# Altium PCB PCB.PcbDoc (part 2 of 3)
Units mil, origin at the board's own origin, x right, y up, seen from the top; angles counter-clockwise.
Board outline 5900 x 2310 mil, 2 copper layers (Top Layer, Bottom Layer), stack 62 mil thick; 158 components, 83 nets, 407 pads, 547 vias.
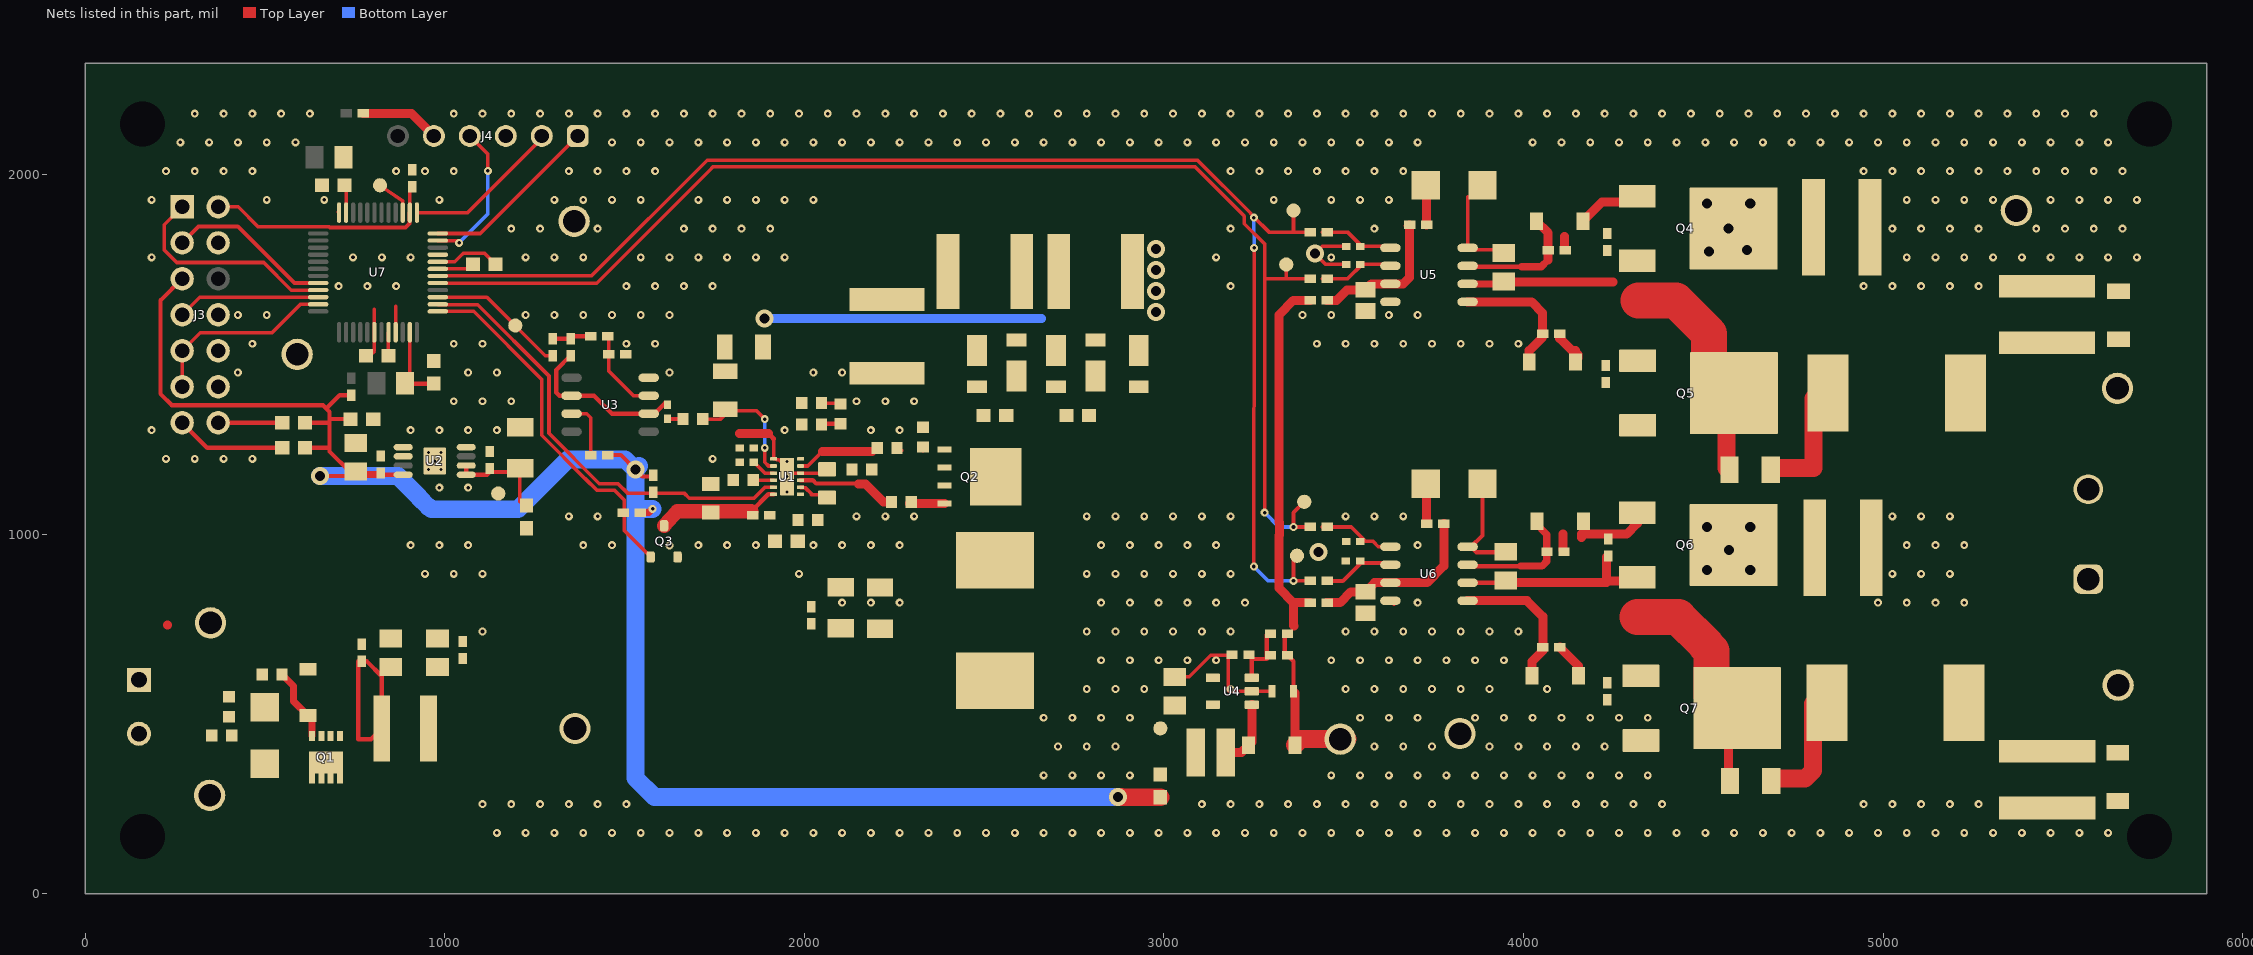
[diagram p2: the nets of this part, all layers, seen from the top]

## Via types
v1: diameter 22, hole 10, Top Layer to Bottom Layer, 506 vias
v2: diameter 50, hole 28, Top Layer to Bottom Layer, tented both sides, 22 vias
v3: diameter 22, hole 10, Top Layer to Bottom Layer, tented both sides, 11 vias
v4: diameter 19.68, hole 7.87, Top Layer to Bottom Layer, tented both sides, 8 vias

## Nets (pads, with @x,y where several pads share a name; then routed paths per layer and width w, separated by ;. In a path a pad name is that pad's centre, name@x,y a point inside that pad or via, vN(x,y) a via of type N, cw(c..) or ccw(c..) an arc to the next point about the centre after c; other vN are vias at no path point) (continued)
GND: C2.2 C3.2 C4.2 C5.2 C9.1 C10.2 C11.2 C12.2 C14.1 C15.2 C16.2 C17.2 C18.2 C19.2 C20.2 C21.2 C22.2 C23.2 C24.2 C25.2 C26.2 C28.2 C31.2 C32.2 C33.2 C34.2 C35.2 C36.2 C38.2 C39.2 C40.2 C41.2 C42.2 C43.2 C44.2 C45.2 C46.2 C47.2 C48.2 D3.2 J1.1 J3.4 J3.8 J3.10 J3.12 J4.3 Q3.2 Q5.3 Q7.3 R1.1 R9.1 R10.1 R11.1 R15.1 R23.1 R31.1 R39.1 R43.1 TP5.1 TP6.1 TP7.1 TP8.1 U1.4 U1.7 U1.13@1952.05,1160 U2.4 U2.5 U2.6 U2.9 U3.4 U4.2 U5.4 U6.4 U7.12 U7.30 U7.33 U7.44 U7.45 | length 1319.8
  Top Layer w10: U7.12@704.64,1895.75 U7.12@706.25,1894.14 ; C47.2@780.97,1495.75 790.97,1495.75 804.68,1509.45 U7.30@804.68,1561.46 804.68,1624.68 ; U7.33@863.73,1561.46 863.73,1633.73 ; U7.44@980.86,1757.32 1027.76,1757.32 1050.43,1780 1051.91,1780 1053.49,1781.57 1109.92,1781.57 C48.2@1141.5,1750 ; 1914.65,1265.35 U1.7@1914.65,1209.21 1920.24,1209.21 1921.05,1208.4 1922.46,1208.4 1923.54,1207.32 1928.67,1207.32 1937.36,1198.63 1937.36,1186.5 U1.13@1952.05,1171.81 ; v4(1952.05,1202.32) U1.13@1952.44,1202.72 ; U1.13@1961.89,1169.84 U1.4@1989.45,1169.84 C14.1@2057.4,1169.84 ; C14.1@2063.3,1180.5 C14.1@2063.3,1193.3 ; C26.2@3030,603.29 3070,603.29 3130,663.29 R23.1@3186.38,663.29 ; R23.1@3178.66,655.57 3178.66,564.78 3180.16,563.29 U4.2@3244.13,563.29 C28.2@3300,563.29 ; C36.2@3503.15,1750 3450,1750 v2(3420,1780) 3440,1800 C33.2@3503.15,1800 ; U6.4@3639.48,805 U6.4@3639.48,815
  Top Layer w14: 1900,1280 1914.65,1265.35
  Top Layer w25: 229.87,747 230,747.13 ; 1820,1280 1900,1280
  other v1: 1145.19,169.5 1225.19,169.5 1305.19,169.5 1385.19,169.5 1465.19,169.5 1545.19,169.5 1625.19,169.5 1705.19,169.5 1785.19,169.5 1865.19,169.5 1945.19,169.5 2025.19,169.5 2105.19,169.5 2185.19,169.5 2265.19,169.5 2345.19,169.5 2425.19,169.5 2505.19,169.5 2585.19,169.5 2665.19,169.5 2745.19,169.5 2825.19,169.5 2905.19,169.5 2985.19,169.5 3065.19,169.5 3145.19,169.5 3225.19,169.5 3305.19,169.5 3385.19,169.5 3465.19,169.5 3545.19,169.5 3625.19,169.5 3705.19,169.5 3785.19,169.5 3865.19,169.5 3945.19,169.5 4025.19,169.5 4105.19,169.5 4185.19,169.5 4265.19,169.5 4345.19,169.5 4425.19,169.5 4505.19,169.5 4585.19,169.5 4665.19,169.5 4745.19,169.5 4825.19,169.5 4905.19,169.5 4985.19,169.5 5065.19,169.5 5145.19,169.5 5225.19,169.5 5305.19,169.5 5385.19,169.5 5465.19,169.5 5545.19,169.5 5625.19,169.5 1105.19,249.5 1185.19,249.5 1265.19,249.5 1345.19,249.5 1425.19,249.5 1505.19,249.5 3105.19,249.5 3185.19,249.5 3265.19,249.5 3345.19,249.5 3425.19,249.5 3505.19,249.5 3585.19,249.5 3665.19,249.5 3745.19,249.5 3825.19,249.5 3905.19,249.5 3985.19,249.5 4065.19,249.5 4145.19,249.5 4225.19,249.5 4305.19,249.5 4385.19,249.5 4945.19,249.5 5025.19,249.5 5105.19,249.5 5185.19,249.5 5265.19,249.5 2665.19,329.5 2745.19,329.5 2825.19,329.5 2905.19,329.5 3465.19,329.5 3545.19,329.5 3625.19,329.5 3705.19,329.5 3785.19,329.5 3865.19,329.5 3945.19,329.5 4025.19,329.5 4105.19,329.5 4185.19,329.5 4265.19,329.5 4345.19,329.5 2705.19,409.5 2785.19,409.5 2865.19,409.5 3585.19,409.5 3665.19,409.5 3745.19,409.5 3905.19,409.5 3985.19,409.5 4065.19,409.5 4145.19,409.5 4225.19,409.5 2665.19,489.5 2745.19,489.5 2825.19,489.5 2905.19,489.5 3545.19,489.5 3625.19,489.5 3705.19,489.5 3865.19,489.5 3945.19,489.5 4025.19,489.5 4105.19,489.5 4185.19,489.5 4265.19,489.5 4345.19,489.5 2785.19,569.5 2865.19,569.5 2945.19,569.5 3185.19,569.5 3505.19,569.5 3585.19,569.5 3665.19,569.5 3745.19,569.5 3825.19,569.5 3905.19,569.5 4065.19,569.5 2825.19,649.5 2905.19,649.5 2985.19,649.5 3065.19,649.5 3145.19,649.5 3465.19,649.5 3545.19,649.5 3625.19,649.5 3705.19,649.5 3785.19,649.5 3865.19,649.5 3945.19,649.5 1105.19,729.5 2785.19,729.5 2865.19,729.5 2945.19,729.5 3025.19,729.5 3105.19,729.5 3185.19,729.5 3505.19,729.5 3585.19,729.5 3665.19,729.5 3745.19,729.5 3825.19,729.5 3905.19,729.5 3985.19,729.5 2105.19,809.5 2185.19,809.5 2265.19,809.5 2825.19,809.5 2905.19,809.5 2985.19,809.5 3065.19,809.5 3145.19,809.5 3225.19,809.5 3705.19,809.5 4985.19,809.5 5065.19,809.5 5145.19,809.5 5225.19,809.5 945.19,889.5 1025.19,889.5 1105.19,889.5 1985.19,889.5 2785.19,889.5 2865.19,889.5 2945.19,889.5 3025.19,889.5 3105.19,889.5 3185.19,889.5 5025.19,889.5 5105.19,889.5 5185.19,889.5 1625,968.5 905.19,969.5 985.19,969.5 1065.19,969.5 1385.19,969.5 1465.19,969.5 1705.19,969.5 1785.19,969.5 1865.19,969.5 2025.19,969.5 2105.19,969.5 2185.19,969.5 2265.19,969.5 2825.19,969.5 2905.19,969.5 2985.19,969.5 3065.19,969.5 3145.19,969.5 3705.19,969.5 5065.19,969.5 5145.19,969.5 5225.19,969.5 1345.19,1049.5 1425.19,1049.5 2145.19,1049.5 2225.19,1049.5 2305.19,1049.5 2785.19,1049.5 2865.19,1049.5 2945.19,1049.5 3025.19,1049.5 3105.19,1049.5 3185.19,1049.5 3505.19,1049.5 3585.19,1049.5 3665.19,1049.5 5025.19,1049.5 5105.19,1049.5 5185.19,1049.5 985.19,1129.5 1065.19,1129.5 225.19,1209.5 305.19,1209.5 385.19,1209.5 465.19,1209.5 1745.19,1209.5 185.19,1289.5 905.19,1289.5 985.19,1289.5 1065.19,1289.5 1145.19,1289.5 1945.19,1289.5 2185.19,1289.5 2265.19,1289.5 1025.19,1369.5 1105.19,1369.5 1185.19,1369.5 2145.19,1369.5 2225.19,1369.5 2305.19,1369.5 425.19,1449.5 1065.19,1449.5 1145.19,1449.5 1625.19,1449.5 2025.19,1449.5 2105.19,1449.5 465.19,1529.5 1025.19,1529.5 1105.19,1529.5 1505.19,1529.5 1585.19,1529.5 3425.19,1529.5 3505.19,1529.5 3585.19,1529.5 3665.19,1529.5 3745.19,1529.5 3825.19,1529.5 3905.19,1529.5 3985.19,1529.5 425.19,1609.5 505.19,1609.5 1225.19,1609.5 1305.19,1609.5 1385.19,1609.5 1465.19,1609.5 1545.19,1609.5 1625.19,1609.5 3385.19,1609.5 3465.19,1609.5 3625.19,1609.5 3705.19,1609.5 705.19,1689.5 785.19,1689.5 865.19,1689.5 1505.19,1689.5 1585.19,1689.5 1665.19,1689.5 1745.19,1689.5 3185.19,1689.5 4945.19,1689.5 5025.19,1689.5 5105.19,1689.5 5185.19,1689.5 5265.19,1689.5 185.19,1769.5 745.19,1769.5 825.19,1769.5 905.19,1769.5 1225.19,1769.5 1305.19,1769.5 1385.19,1769.5 1545.19,1769.5 1625.19,1769.5 1705.19,1769.5 1785.19,1769.5 1865.19,1769.5 1945.19,1769.5 3145.19,1769.5 3465.19,1769.5 5065.19,1769.5 5145.19,1769.5 5225.19,1769.5 5305.19,1769.5 5385.19,1769.5 5465.19,1769.5 5545.19,1769.5 5625.19,1769.5 5705.19,1769.5 1185.19,1849.5 1265.19,1849.5 1425.19,1849.5 1665.19,1849.5 1745.19,1849.5 1825.19,1849.5 1905.19,1849.5 3185.19,1849.5 3585.19,1849.5 5025.19,1849.5 5105.19,1849.5 5185.19,1849.5 5265.19,1849.5 5425.19,1849.5 5505.19,1849.5 5585.19,1849.5 5665.19,1849.5 185.19,1929.5 505.19,1929.5 665.19,1929.5 985.19,1929.5 1305.19,1929.5 1385.19,1929.5 1465.19,1929.5 1545.19,1929.5 1705.19,1929.5 1785.19,1929.5 1865.19,1929.5 1945.19,1929.5 2025.19,1929.5 3305.19,1929.5 3465.19,1929.5 3545.19,1929.5 3625.19,1929.5 5065.19,1929.5 5145.19,1929.5 5225.19,1929.5 5305.19,1929.5 5465.19,1929.5 5545.19,1929.5 5625.19,1929.5 5705.19,1929.5 225.19,2009.5 305.19,2009.5 385.19,2009.5 465.19,2009.5 865.19,2009.5 945.19,2009.5 1025.19,2009.5 1345.19,2009.5 1425.19,2009.5 1505.19,2009.5 1585.19,2009.5 3185.19,2009.5 3265.19,2009.5 3345.19,2009.5 3425.19,2009.5 3505.19,2009.5 3585.19,2009.5 3665.19,2009.5 4945.19,2009.5 5025.19,2009.5 5105.19,2009.5 5185.19,2009.5 5265.19,2009.5 5345.19,2009.5 5425.19,2009.5 5505.19,2009.5 5585.19,2009.5 5665.19,2009.5 265.19,2089.5 345.19,2089.5 425.19,2089.5 505.19,2089.5 585.19,2089.5 1465.19,2089.5 1545.19,2089.5 1625.19,2089.5 1705.19,2089.5 1785.19,2089.5 1865.19,2089.5 1945.19,2089.5 2025.19,2089.5 2105.19,2089.5 2185.19,2089.5 2265.19,2089.5 2345.19,2089.5 2425.19,2089.5 2505.19,2089.5 2585.19,2089.5 2665.19,2089.5 2745.19,2089.5 2825.19,2089.5 2905.19,2089.5 2985.19,2089.5 3065.19,2089.5 3145.19,2089.5 3225.19,2089.5 3305.19,2089.5 3385.19,2089.5 3465.19,2089.5 3545.19,2089.5 3625.19,2089.5 3705.19,2089.5 4025.19,2089.5 4105.19,2089.5 4185.19,2089.5 4265.19,2089.5 4345.19,2089.5 4425.19,2089.5 4505.19,2089.5 4585.19,2089.5 4665.19,2089.5 4745.19,2089.5 4825.19,2089.5 4905.19,2089.5 4985.19,2089.5 5065.19,2089.5 5145.19,2089.5 5225.19,2089.5 5305.19,2089.5 5385.19,2089.5 5465.19,2089.5 5545.19,2089.5 5625.19,2089.5 305.19,2169.5 385.19,2169.5 465.19,2169.5 545.19,2169.5 625.19,2169.5 1025.19,2169.5 1105.19,2169.5 1185.19,2169.5 1265.19,2169.5 1345.19,2169.5 1425.19,2169.5 1505.19,2169.5 1585.19,2169.5 1665.19,2169.5 1745.19,2169.5 1825.19,2169.5 1905.19,2169.5 1985.19,2169.5 2065.19,2169.5 2145.19,2169.5 2225.19,2169.5 2305.19,2169.5 2385.19,2169.5 2465.19,2169.5 2545.19,2169.5 2625.19,2169.5 2705.19,2169.5 2785.19,2169.5 2865.19,2169.5 2945.19,2169.5 3025.19,2169.5 3105.19,2169.5 3185.19,2169.5 3265.19,2169.5 3345.19,2169.5 3425.19,2169.5 3505.19,2169.5 3585.19,2169.5 3665.19,2169.5 3745.19,2169.5 3825.19,2169.5 3905.19,2169.5 3985.19,2169.5 4065.19,2169.5 4145.19,2169.5 4225.19,2169.5 4305.19,2169.5 4385.19,2169.5 4465.19,2169.5 4545.19,2169.5 4625.19,2169.5 4705.19,2169.5 4785.19,2169.5 4865.19,2169.5 4945.19,2169.5 5025.19,2169.5 5105.19,2169.5 5185.19,2169.5 5265.19,2169.5 5345.19,2169.5 5425.19,2169.5 5505.19,2169.5 5585.19,2169.5
  other v2: 3430,950
  other v4: 1952.05,1117.68 1952.05,1160 954.57,1180 990,1180 972.28,1203.62 954.57,1227.24 990,1227.24
GPIO_12: J4.4 U7.47 | length 412.8
  Top Layer w10: U7.47@980.86,1816.38 1033.62,1816.38 v3(1040,1810) ; J4.4@1070,2107.12 1120,2057.12 v3(1120,2010)
  Bottom Layer w10: v3(1040,1810) 1120,1890 v3(1120,2010)
GPIO_PGOOD: R6.1 U1.11 U7.38 | length 1263.2
  Top Layer w10: U7.38@980.86,1639.21 981.76,1638.31 1091.69,1638.31 1290,1440 1290,1280.54 1430.04,1140.5 1482,1140.5 1508.21,1114.29 1665.42,1114.29 1679.71,1100 1860,1100 1890.47,1130.47 U1.11@1914.65,1130.47
GPIO_UVLO_FET: Q3.1 R5.1 U7.37 | length 1015.5
  Top Layer w10: U7.37@980.86,1619.53 1080.47,1619.53 1270,1430 1270,1274.68 1391.06,1153.62 1391.64,1153.62 1422.64,1122.63 1471.87,1122.63 1499.29,1095.21 1499.29,1010 Q3.1@1572.6,936.69
HV: C6.1 C31.1 C38.1 D1.1 Q4.4 Q6.4 R8.2 | length 813.7
  Top Layer w25: Q6.4@4583.86,970 Q6.4@4613.86,940
  Bottom Layer w25: v2(1888.98,1599.5) 2659.5,1599.5 2660,1600
  other v2: 4510,900 4630,900 4571,955.5 4510,1020 4630,1020 2978,1618 2978,1676.5 2978,1735.03 4515.94,1786.02 4621.19,1790 2978,1792.5 4570,1850 4510,1920 4630,1920
NetC1_1: C1.1 D1.2 D4.1
NetC1_2: C1.2 C7.1 D5.2 D6.1
NetC2_1: C2.1 C3.1 D2.1 L1.1 Q1.1 Q1.2 Q1.3 | length 520.9
  Top Layer w12: 760,430 795,430 L1.1@825,460 825,605 783.62,646.38 C2.1@770,646.38 760,646.38 760,430
NetC6_2: C6.2 C13.1 D4.2 D5.1
NetC7_2: C7.2 D7.2 L2.2 Q2.5
NetC8_2: C8.2 C9.2
NetC13_2: C13.2 C16.1 D6.2 D7.1
NetC14_2: C14.2 U1.2 | length 94.4
  Top Layer w10: U1.2@1989.45,1130.47 1990.26,1129.66 1997.27,1129.66 1998.35,1128.58 2003.47,1128.58 2020,1112.05 2020,1110 2060,1110 C14.2@2070,1100
NetC15_1: C15.1 R2.2 U1.1
NetC17_1: C17.1 R7.1 U1.5 | length 230
  Top Layer w10: U1.5@1989.45,1189.53 2009.53,1189.53 2050,1230 ; R7.1@2188.5,1230 R7.1@2198.5,1240
  Top Layer w25: 2050,1230 R7.1@2188.5,1230
NetC18_1: C18.1 U1.9 | length 67.5
  Top Layer w10: C18.1@1859.68,1200 1860,1200 1890.16,1169.84 U1.9@1914.65,1169.84
NetC21_1: C21.1 C22.1 R13.1 TP3.1 U2.1 U2.2 | length 236.8
  Top Layer w10: 1208.5,1090 1208.5,1181.42 C22.1@1210,1182.91
  Top Layer w12: U2.1@1059.88,1165.24 U2.2@1059.88,1190.83 ; U2.1@1085.47,1165.24 1117.52,1165.24 1122.28,1170 1125.2,1172.91 C22.1@1200,1172.91
NetC23_1: C23.1 R17.2 U1.6 | length 53.5
  Top Layer w12: C23.1@2047.56,1304.43 2050,1306.87 R17.2@2100,1306.87
NetC24_1: C24.1 R17.1 | length 53.5
  Top Layer w10: C24.1@2047.56,1364.43 2097.56,1364.43 R17.1@2100,1361.99
NetC25_1: C25.1 R21.2 U3.3 | length 236.8
  Top Layer w10: R21.2@1453.62,1550 1456.38,1547.24 C25.1@1456.38,1500 1456.38,1453.62 1525,1385 U3.3@1567.28,1385
NetC26_1: C26.1 L3.1 R19.1 TP10.1 U4.4 U4.5
NetC27_2: C27.2 R22.1 R23.2 U4.3 | length 161.5
  Top Layer w12: U4.3@3244.13,600.69 3244.13,652.78 3285.87,652.78 C27.2@3285.87,720.49
NetC29_1: C29.1 R16.1 U3.2 U3.6 | length 456.8
  Top Layer w12: C29.1@1350,1496.38 1310.3,1456.68 1310.3,1394.03 1319.33,1385 U3.6@1352.72,1385 1415.32,1385 1465.32,1335 U3.2@1567.28,1335 1583.35,1335 R16.1@1611.97,1363.62
NetC29_2: C29.2 R20.2 R21.1 | length 109
  Top Layer w12: R20.2@1300,1543.62 C29.2@1350,1543.62 1356.38,1550 R21.1@1406.38,1550
NetC30_1: C30.1 Q4.3 Q5.4 R27.1 R45.1 U5.6 | length 1106.5
  Top Layer w10: Q4.3@4312.91,1760.24 Q4.3@4316.14,1760.24
  Top Layer w20: U5.6@3844.05,1695.87 3945.05,1695.87 C30.1@3950.76,1701.58
  Top Layer w25: C30.1@3950.76,1701.58 4247.89,1701.18 ; Q5.4@4563.91,1371.43 4565.45,1372.97 Q5.4@4584.72,1392.24
  Top Layer w50: R45.1@4563.91,1183.5 Q5.4@4563.91,1371.43
  Top Layer w75: Q5.4@4515.68,1381 4565.45,1372.97 4581.2,1370.43 Q5.4@4583.86,1370
  Top Layer w100: 4319.37,1649.13 4423.85,1649.13 4515.68,1557.3 Q5.4@4515.68,1381
NetC30_2: C30.2 D9.1 U5.8 | length 238
  Top Layer w10: U5.8@3844.05,1795.87 3844.05,1938.54 ; U5.8@3849.05,1790.87 C30.2@3944.34,1790.87
NetC32_1: C32.1 R24.1 R25.1 U5.3 | length 428.2
  Top Layer w10: C32.1@3546.77,1679.53 C32.1@3563.11,1695.87 ; R25.1@3670.91,1857.76 R25.1@3673.15,1860
  Top Layer w25: R24.1@3453.62,1650 3480,1650 3509.53,1679.53 3546.77,1679.53 C32.1@3560,1679.53 3576.34,1695.87 U5.3@3629.49,1695.87 3664.83,1695.87 3683.15,1714.18 R25.1@3683.15,1860
NetC33_1: C33.1 R28.2 U5.1 | length 201.5
  Top Layer w10: R28.2@3440.39,1840 3510.39,1840 3550.39,1800 U5.1@3625.35,1800
NetC34_1: C34.1 C35.1 J2.2 L4.2 TP13.1
NetC36_1: C36.1 R29.2 U5.2 | length 207.4
  Top Layer w10: R29.2@3440.39,1710 3510.39,1710 3550.39,1750 3625.35,1750 U5.2@3629.49,1745.87
NetC37_1: C37.1 Q6.3 Q7.4 R35.1 R46.1 U6.6 | length 1153.4
  Top Layer w12: U6.6@3854.05,865 C37.1@3949.34,865
  Top Layer w25: C37.1@3949.34,865 4230,865 4230,870 ; R35.1@4230,936.38 4230,870 ; Q6.3@4286.38,870 4230,870 ; R46.1@4569.91,320 4569.91,492.28 Q7.4@4593.86,516.22
  Top Layer w50: Q7.4@4512.5,550 Q7.4@4522,550 ; Q7.4@4524,550 Q7.4@4586.38,550
  Top Layer w100: 4316.14,769.5 4430.35,769.5 4506.5,693.35 4506.5,691.04 4522,675.54 Q7.4@4522,550
NetC37_2: C37.2 D12.1 U6.8 | length 294.5
  Top Layer w12: D12.1@3885.51,1140 3885.51,996.45 3854.05,965 3869.05,950 C37.2@3954.34,950
NetC39_1: C39.1 R32.1 R33.1 U6.3 | length 490.5
  Top Layer w12: R32.1@3450.39,810 R32.1@3450.39,816
  Top Layer w25: R32.1@3453.62,810 3490,810 3519.53,839.53 C39.1@3560,839.53 3585.47,865 U6.3@3629.49,865 3731.46,865 3778.12,911.66 R33.1@3778.12,1029.5
NetC40_1: C40.1 R36.2 U6.1 | length 221.9
  Top Layer w10: R36.2@3440.39,1020 3520.39,1020 3560.39,980 3581.1,980 3596.1,965 U6.1@3639.48,965
NetC41_1: C41.1 C42.1 J2.1 L5.2 TP16.1
NetC43_1: C43.1 R37.2 U6.2 | length 209.3
  Top Layer w12: R37.2@3450.39,870 3497.4,870 C43.1@3547.4,920 ; C43.1@3550,920 3634.48,920 U6.2@3639.48,915
NetC45_1: C45.1 L6.1 U7.35 | length 227.5
  Top Layer w10: L6.1@890,1420 903.1,1433.1 U7.35@903.1,1561.46
  Top Layer w12: L6.1@890,1420 891.5,1418.5 C45.1@970,1418.5
NetC46_1: C46.1 L7.1 U7.11 | length 75.9
  Top Layer w10: C46.1@718.35,1969.29 C46.1@719.84,1967.8 ; U7.11@725.94,1894.14 C46.1@725.94,1967.88
NetC47_1: C47.1 U7.32 | length 75.6
  Top Layer w10: C47.1@843.14,1484.92 U7.32@843.14,1560.55
NetC48_1: C48.1 U7.43 | length 102.8
  Top Layer w10: U7.43@980.86,1737.64 1066.14,1737.64 C48.1@1078.5,1750
NetD2_2: D2.2 Q1.4 R1.2 | length 205.5
  Top Layer w20: R1.2@547.56,610 580,577.56 580,535.53 D2.2@620,495.53 631.06,484.47 Q1.4@631.06,439.06
NetD8_2: D8.2 L3.2 U4.1 | length 188.6
  Top Layer w25: L3.2@3171.34,393.29 3215.53,393.29 D8.2@3235.53,413.29 3244.13,421.89 U4.1@3244.13,525.89
NetD9_2: D9.2 R25.2 | length 111
  Top Layer w25: D9.2@3728.03,1970 3730.39,1967.64 R25.2@3730.39,1860
NetD10_1: D10.1 R26.1 U5.7 | length 357.4
  Top Layer w10: U5.7@3844.05,1745.87 U5.7@3845.54,1744.38
  Top Layer w12: U5.7@3844.05,1745.87 3844.05,1743.38 3993.76,1743.38
  Top Layer w20: 3993.76,1743.38 4048.88,1743.38 4068,1762.5
  Top Layer w25: D10.1@4035.53,1870 4068,1837.53 4068,1762.5
NetD10_2: D10.2 Q4.1 R26.2 R27.2 | length 215.1
  Top Layer w25: R26.2@4113.5,1793.5 4113.5,1827.99 ; D10.2@4164.47,1870 4218.09,1923.62 4300,1923.62 Q4.1@4316.14,1939.76
NetD11_1: D11.1 R30.1 U5.5 | length 373.9
  Top Layer w25: U5.5@3844.05,1645.87 4022.13,1645.87 4053.13,1614.87 4053.13,1547.6 4015.53,1510 ; D11.1@4015.56,1478.5 4015.56,1509.97
NetD11_2: D11.2 Q5.1 R30.2 R31.2 | length 67.3
  Top Layer w25: 4100.37,1544.51 4134.88,1510 4144.47,1510 ; D11.2@4151.24,1490 D11.2@4151.24,1498.96
NetD12_2: D12.2 R33.2 | length 111
  Top Layer w25: D12.2@3728.03,1140 3730.39,1137.63 R33.2@3730.39,1030
NetD13_1: D13.1 R34.1 U6.7 | length 315
  Top Layer w12: U6.7@3854.05,915 3854.05,911.12 3991.58,911.12
  Top Layer w20: 3991.58,911.12 4051.12,911.12 4064.5,924.5 4064.5,998.79 D13.1@4049.79,1013.5
NetD13_2: D13.2 Q6.1 R34.2 R35.2 | length 220.4
  Top Layer w25: R34.2@4109.12,956.5 4109.12,1000.47 ; 4161.24,990.84 4161.24,1000 4286.37,1000 Q6.1@4316.14,1029.76
NetD14_1: D14.1 R38.1 U6.5 | length 404.8
  Top Layer w25: U6.5@3844.05,815 4009.19,815 4053.38,770.81 R38.1@4053.38,686 4053.38,675.88 4023.53,646.03 D14.1@4023.53,605.98
NetD14_2: D14.2 Q7.1 R38.2 R39.2 | length 101.5
  Top Layer w25: R38.2@4100.62,686 4152.47,634.15 D14.2@4152.47,605.98
NetJ3_13: J3.13 R40.1 | length 307.5
  Top Layer w12: J3.13@270,1310 340,1240 R40.1@548.5,1240
NetJ3_14: J3.14 R41.1 | length 178.5
  Top Layer w12: J3.14@370,1310 R41.1@548.5,1310
NetJ4_5: J4.5 R44.2 | length 222.4
  Top Layer w25: R44.2@773.62,2170 907.12,2170 J4.5@970,2107.12
NetL4_1: L4.1 R45.2 | length 311
  Top Layer w50: R45.2@4693,1184 4806.5,1183.5 4806.5,1377.5 L4.1@4809,1380
NetL5_1: L5.1 R46.2 | length 286.4
  Top Layer w50: 4714,320 4782.63,320 4805,342.37 L5.1@4805,528.5
NetQ2_1: Q2.1 Q2.2 Q2.3 R7.2 R11.2 | length 14.3
  Top Layer w12: R7.2@2261.5,1240 R7.2@2269.05,1232.44 ; R11.2@2330,1232.44 R11.2@2332.56,1235
NetQ2_4: Q2.4 R4.2 | length 100.6
  Top Layer w10: R4.2@2290,1082.44 R4.2@2292.56,1085
  Top Layer w25: R4.2@2292.56,1085 Q2.4@2389.57,1085
NetQ3_3: Q3.3 R3.1 R9.2 U1.12 | length 345.2
  Top Layer w12: 1647.01,1060.32 1647.01,1063.62 ; R3.1@1852.76,1063.62 1899.92,1110.79 U1.12@1914.65,1110.79
  Top Layer w40: Q3.3@1610,1023.31 1647.01,1063.62 R3.1@1852.76,1063.62
NetR4_1: R4.1 U1.3 | length 277.4
  Top Layer w12: U1.3@1989.45,1150.16 2023.72,1150.16 2032.75,1141.13 2148.87,1141.13 2150,1140
  Top Layer w25: 2150,1140 2170,1140 2220,1090 R4.1@2241.95,1090
NetR8_1: R8.1 R12.2
NetR10_2: R10.2 U1.10 | length 57.2
  Top Layer w10: R10.2@1857.56,1150 1857.72,1150.16 U1.10@1914.65,1150.16
NetR12_1: R12.1 R14.1 R15.2 U1.8 | length 340.4
  Top Layer w10: R14.1@1717.56,1320 1767.09,1320 1790,1342.91 1867.09,1342.91 v3(1890,1320) ; v3(1890,1240) 1890,1200 1900.47,1189.53 U1.8@1914.65,1189.53
  Bottom Layer w10: v3(1890,1240) v3(1890,1320)
NetR14_2: R14.2 R16.2 | length 43.9
  Top Layer w12: R16.2@1620,1316.38 1623.62,1320 R14.2@1662.44,1320
NetR18_1: R18.1 U3.7 | length 162
  Top Layer w10: U3.7@1352.72,1335 1395,1335 1406.38,1323.62 R18.1@1406.38,1220
NetTP18_1: TP18.1 U7.3 | length 109.3
  Top Layer w10: TP18.1@820,1970 883.42,1926.58 U7.3@883.42,1894.14
nTRST: J3.2 R43.2 U7.2 | length 671.9
  Top Layer w10: J3.2@370,1910 425.79,1910 480.95,1854.84 678.6,1854.84 680.72,1852.72 891.19,1852.72 902.2,1863.72 U7.2@902.2,1893.23 ; U7.2@903.1,1894.14 903.1,1962.76 R43.2@912.47,1972.13
PWM_Bridge_1: R28.1 R37.1 TP12.1 TP17.1 U7.42 | length 3920.7
  Top Layer w10: U7.42@981.76,1718.86 1053.05,1718.86 1053.49,1718.43 1408.43,1718.43 1730,2040 3093.28,2040 3241.37,1891.9 3241.37,1890.63 v3@3250,1882 ; v3(3250,910) v3(3250.5,1796.01) ; v3(3250,1880) v3@3250,1882 ; TP12.1@3360,1900 3360,1840 ; TP17.1@3370,940 3360,930 v3(3360,870) R37.1@3406.38,870 ; R28.1@3406.38,1840 3360,1840 ; v3@3250,1882 3292,1840 3360,1840
  Bottom Layer w10: v3(3250,910) 3290,870 v3(3360,870) ; v3(3250,1880) v3(3250.5,1796.01)
PWM_Bridge_2: R29.1 R36.1 TP14.1 TP15.1 U7.41 | length 3673
  Top Layer w10: U7.41@981.76,1697.36 1422.64,1697.36 1734.5,2009.5 1747.13,2022.13 3085.87,2022.13 3223.5,1884.5 3223.5,1863.5 3280,1807 3280,1710 ; v3(3280,1060) 3280,1710 ; TP14.1@3340,1750 3340,1710 ; TP15.1@3390,1090 3360,1060 v3(3360,1020) R36.1@3406.38,1020 ; R29.1@3406.38,1710 3340,1710 ; 3280,1710 3340,1710
  Bottom Layer w10: v3(3280,1060) 3320,1020 v3(3360,1020)
PWM_DAC: R20.1 TP9.1 U7.39 | length 386.5
  Top Layer w10: U7.39@980.86,1658.9 1117.48,1658.9 1280,1496.38 R20.1@1300,1496.38
RX: J4.1 U7.48 | length 501.4
  Top Layer w10: U7.48@980.86,1836.06 1098.95,1836.06 J4.1@1370,2107.12
TCK: J3.9 J3.11 U7.23 | length 531.7
  Top Layer w10: J3.11@270,1410 J3.9@270,1510 320,1560 520,1560 599.21,1639.21 U7.23@648.18,1639.21
TDI: J3.3 U7.20 | length 462
  Top Layer w10: J3.3@270,1810 315.35,1855.35 425.15,1855.35 582.23,1698.27 U7.20@648.18,1698.27
TDO: J3.7 U7.22 | length 398.4
  Top Layer w10: J3.7@270,1610 318.9,1658.9 U7.22@648.18,1658.9
TMS: J3.1 U7.21 | length 615
  Top Layer w10: J3.1@270,1910 220,1860 220,1790 254.65,1755.35 496.65,1755.35 573.42,1678.58 U7.21@648.18,1678.58
TX: J4.2 U7.1 | length 446.6
  Top Layer w10: U7.1@922.79,1894.14 1064.14,1894.14 J4.2@1280,2110
V3p3: C19.1 C20.1 C44.1 J3.5 R5.2 R6.2 R18.2 R19.2 R40.2 R41.2 R42.1 TP4.1 U2.8 | length 5222.1
  Top Layer w12: J3.5@270,1710 210,1650 210,1390 241.5,1358.5 661.5,1358.5 670.75,1349.25 ; R40.2@611.5,1240 680,1240 ; R41.2@611.5,1310 680,1310 ; v2(652.76,1161.5) 829.22,1161.5 830,1162.28 C20.1@827.05,1165.24 ; C44.1@738.5,1320 680,1320 ; R42.1@740,1386.38 707.87,1386.38 670.75,1349.25 ; U2.8@884.68,1165.24 C20.1@827.05,1165.24 ; R18.2@1453.62,1220 1490,1220 v2(1530,1180) 1549.5,1160.5 1576.88,1160.5 R6.2@1580,1163.62 ; 670.75,1349.25 680,1340 680,1320 ; 680,1240 680,1230 736.38,1173.62 C19.1@752.6,1173.62 756.22,1170 C20.1@822.28,1170 C20.1@827.05,1165.24 ; 680,1240 680,1310 ; 680,1310 680,1320
  Top Layer w20: R5.2@1543.62,1060 1567.5,1060 v3(1578,1070.5)
  Top Layer w50: v2(2872.5,269) 2881.51,269 2882,268.5 R19.2@2990,268.5
  Bottom Layer w50: v2(652.76,1161.5) 870.5,1161.5 928.63,1103.37 928.63,1101.83 954.33,1076.13 955.87,1076.13 962.71,1069.29 1203.54,1069.29 1342.26,1208 1502,1208 v2(1530,1180) ; v2@1540,1190 v2(1530,1180) ; v3(1578,1070.5) 1540.5,1070.5 1530,1060 ; v2(2872.5,269) 1583,269 1530,322 1530,1060 ; 1530,1060 v2(1530,1180)
V12p0: C27.1 C28.1 D8.1 R22.2 R24.2 R32.2 TP11.1 | length 1500.7
  Top Layer w12: C27.1@3335.91,723.29 3335.91,671 R22.2@3343.62,663.29 3360,646.91 C28.1@3360,563.29
  Top Layer w25: 3361.5,744.94 3360,746.44 3360,810 ; D8.1@3364.47,413.29 C28.1@3364.47,558.82 ; R32.2@3406.38,810 3360,810 ; R24.2@3406.38,1650 3360,1650 3320,1610 3320,1034.37 3321.37,1033 3321.37,997 3320,995.63 3320,850 3360,810
  Top Layer w50: D8.1@3364.47,413.29 3381.18,430 TP11.1@3510,430
VBAT: C8.1 D3.1 J1.2 Q1.5 Q1.6 Q1.7 Q1.8 Q1.9 TP1.1
Vcc: C4.1 C5.1 C10.1 C11.1 C12.1 L1.2 L2.1 R2.1 R3.2 R13.2 TP2.1
pads on no net: J3.6 LBL1.0 U1.13@1952.05,1133.03 U1.13@1952.05,1186.97 U2.3 U2.7 U3.1 U3.5 U3.8 U7.4 U7.5 U7.6 U7.7 U7.8 U7.10 U7.13 U7.14 U7.15 U7.16 U7.17 U7.18 U7.19 U7.24 U7.25 U7.26 U7.27 U7.28 U7.29 U7.31 U7.34 U7.36 U7.40 U7.46

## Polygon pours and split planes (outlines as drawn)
NetL4_1 on Top Layer "TOP_LAYER_NETL4_1_P140" (solid, remove dead copper, pour order 140): 4662,1212 4666,1216 4745.5,1216 4775.5,1246 4775.5,1498 4901,1498 4901,1223 4817,1139 4662,1139
NetL5_1 on Top Layer "TOP_LAYER_NETL5_1_P034" (solid, remove dead copper, pour order 34): 4662,350.5 4666,354.5 4745.5,354.5 4775.5,384.5 4775.5,636.5 4901,636.5 4901,361.5 4817,277.5 4662,277.5
NetC37_1 on Top Layer "TOP_LAYER_NETC37_1_P046" (solid, remove dead copper, pour order 46): 4474,420.5 4613,420.5 4613,276 4598.5,276 4474,276
no net on Top Layer "TOP_LAYER_NONET_P136" (solid, remove dead copper, pour order 136): 4445.5,1202
NetC30_1 on Top Layer "TOP_LAYER_NETC30_1_P072" (solid, remove dead copper, pour order 72): 4463,1292.5 4620,1292.5 4620,1142 4463,1142
GND on Top Layer "TOP_LAYER_GND_P138" (solid, remove dead copper, pour order 138): 74.41,2094.5 194.95,2187.5 5684.9,2187.5 5752,2120.4 5752,144.55 5689.93,82.47 189.93,82.47 74.41,179.5
HV on Top Layer "TOP_LAYER_HV_P074" (solid, remove dead copper, pour order 74): 4727,1094.5 4840.5,1094.5 4840.5,827 4837.55,827 4741,827 4705,855.5 4705,1084
NetC13_2 on Top Layer "TOP_LAYER_NETC13_2_P134" (solid, remove dead copper, pour order 134): 2125,1621 2125,1767 2200.17,1842.17 2509,1842.17 2509,1621
HV on Top Layer "TOP_LAYER_HV_P084" (solid, remove dead copper, pour order 84): 4726.87,1987 4840.87,1987 4840.87,1719.5 4837.92,1719.5 4726.87,1719.5 4699.87,1736.5 4699.87,1964.5
HV on Top Layer "TOP_LAYER_HV_P132" (solid, remove dead copper, pour order 132): 4739.5,892.5
NetC23_1 on Top Layer "TOP_LAYER_NETC23_1_P126" (solid, remove dead copper, pour order 126): 2118.7,1300 2000,1210 1980,1210 1980,1220 2032.8,1272.8 2032.8,1300
NetQ2_1 on Top Layer "TOP_LAYER_NETQ2_1_P118" (solid, remove dead copper, pour order 118): 2240,1258.7 2396.8,1258.7 2409.56,1245.94 2409.56,1125.94 2401,1125.94 2360,1125.94 2360,1130 2360,1172.91 2321.46,1211.46 2240,1211.46
V3p3 on Top Layer "TOP_LAYER_V3P3_P102" (solid, remove dead copper, pour order 102): 510,1550 550,1570 680,1570 700,1550 700,1410 751.65,1410 761.65,1400 760,1398.35 760,1291.46 756.17,1287.62 712.6,1287.62 712.6,1213.62 716.22,1210 913.24,1210 913.24,1121.5 499.01,1121.5
GND on Top Layer "TOP_LAYER_GND_P100" (solid, remove dead copper, pour order 100): 2970,570 2960,580 2960,690 3161.92,690 3195.1,690 3210,675.1 3210,590 3220,580 3221.97,581.97 3308.37,581.97 3308.37,544.65 3303.72,540 3180,540 3170,550 3170,632.42 3160.79,641.63 3159.15,640 3106.71,640 3080,613.29 3080,580 3070,570
NetC26_1 on Top Layer "TOP_LAYER_NETC26_1_P098" (solid, remove dead copper, pour order 98): 3150,620 3158.53,611.47 3158.53,500.95 3150,492.42 3130,492.42 3130,490 3120,480 3120,320 3110,310 2970,310 2960,320 2960,540 2970,550 3100,550 3100,612.68 3107.32,620
NetC30_2 on Top Layer "TOP_LAYER_NETC30_2_P086" (solid, remove dead copper, pour order 86): 3810,2010 3813.46,2006.54 3813.46,1760 3980,1760 3980,2010
NetC37_2 on Top Layer "TOP_LAYER_NETC37_2_P096" (solid, remove dead copper, pour order 96): 3813.46,1180.5 3980.94,1180.5 3980.94,928.5 3813.46,928.5
NetC21_1 on Top Layer "TOP_LAYER_NETC21_1_P116" (solid, remove dead copper, pour order 116): 1031.24,1152.04 1031.24,1198.62 1155.5,1198.62 1174.57,1210 1246.26,1210 1257.64,1198.62 1257.64,1148.86 1257.64,1051.81 1138.19,1051.81 1120,1070 1120,1152.04
Vcc on Top Layer "TOP_LAYER_VCC_P012" (solid, remove dead copper, pour order 12): 952.54,670 941.06,658.52 941.06,560 941.06,370 991.06,320 2640,320 2640,670.18 2288,670.19 2288,767.49 1940,767.49 1940,1071.79 1887.75,1071.79 1888.25,874.49 1301,871.5 1302.45,1037.03 1163.54,1036.53 1161,670.19
VBAT on Top Layer "TOP_LAYER_VBAT_P130" (solid, remove dead copper, pour order 130): 74.41,457.21 94.41,477.21 353.11,477.21 360.32,470.01 370,470.01 370,410 372.79,407.21 710.35,407.21 744.41,373.15 744.41,190 74.41,190
NetC2_1 on Top Layer "TOP_LAYER_NETC2_1_P128" (solid, remove dead copper, pour order 128): 591.5,642.97 608.53,660 880,660 890,650 890,600 870,600 850,580 850,368.5 795,368.5 792,371.5 792,395.58 767.58,420 650,420 650,450 660,460 660,570 640,590 590,590
GND on Bottom Layer "BOTTOM_LAYER_GND_P104" (solid, remove dead copper, pour order 104): 93.5,2078.7 213.5,2198.7 5713.5,2198.7 5750.82,2161.37 5750.82,126.02 5717.3,92.5 219.7,92.5 93.5,218.7
HV on Bottom Layer "BOTTOM_LAYER_HV_P076" (solid, remove dead copper, pour order 76): 2650,1810 2700,1860 3020,1860 3050,1830 3050,1620 3259.5,1410.5 4080.5,1410.5 4290,1620 4290,1920 4356,1986 4684,1986 4730,1940 4730,885.86 4704.14,860 4373,860 4310,923 4310,1130 4257.09,1182.91 2787.09,1182.91 2650,1320

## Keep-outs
Keep-Out Layer:
  text ".Layer_Name" at 577,-858.49 h60

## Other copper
Top Layer:
  rectangle net NetC41_1: 5163,360 5755,647
  rectangle net Vcc: 2283,515 2635.13,671.5
  rectangle net NetC34_1: 5392.83,1085.63 5755,1289.5
  rectangle net NetC41_1: 5393,630.5 5755.5,919.5
  rectangle net NetC37_1: 4212,719.5 4390.94,958.31
  rectangle net NetD14_2: 4132.6,570.18 4376.5,639.5
  rectangle net NetC1_1: 2772.52,1307.88 2860.39,1490
  rectangle net NetR8_1: 1743.5,1430 1815.43,1555.43
  rectangle net HV: 1854.5,1484.59 1915,1630
  rectangle net NetC45_1: 870,1390.02 997.2,1448.54
  rectangle net NetD11_2: 4126.1,1450 4370,1519.13
  rectangle net NetC6_2: 2670,1460 2740,1690
  rectangle net NetC15_1: 1980,1080 2000,1110
  rectangle net NetC15_1: 1960,961 2002,1091.99
  rectangle net NetC23_1: 2032.8,1291.63 2112.8,1321.63
  rectangle net NetC24_1: 2032.8,1343.76 2112.8,1381.63
  rectangle net NetR12_1: 1840,1220 1900,1253.78
  rectangle net GND: 2040,1161.3 2150,1200
  rectangle net GND: 1711.46,1120 1830,1290
  rectangle net NetC17_1: 2170,1161.3 2220,1258.7
  rectangle net NetC1_2: 2540,1306.79 2628,1490
  rectangle net NetC13_2: 2441,1510 2630,1580
  rectangle net NetC7_2: 2440,1240 2520,1430
  rectangle net NetC7_2: 2440,850 2637,1260
  rectangle net NetC46_1: 695.13,1949.12 748.33,2077.08
  rectangle net NetD8_2: 3192.99,330.3 3310,533.29
  rectangle net NetC27_2: 3220,593.29 3313,753.29
  rectangle net V12p0: 3324.5,330 3420,830
  rectangle net NetC1_2: 2660,1308.2 2750,1430
  rectangle net NetC6_2: 2670,1510 2850,1580
  rectangle net NetC1_1: 2780,1310 2980,1430
  rectangle net NetC6_2: 2570,1620 2740,1840
  rectangle net HV: 2880,1460 3012.5,1836.06
  rectangle net NetR12_1: 1710,1301.32 1910,1390
  rectangle net NetC13_2: 2440,1460 2510,1833.35
  rectangle net NetC13_2: 2420,1626.65 2480,1833.35
  rectangle net NetC34_1: 5169.5,1282 5755,1570
  rectangle net NetD13_2: 4096.5,972 4390.5,1098
  rectangle net NetD10_2: 4101.5,1819 4395,1973.51
  rectangle net NetC30_1: 4208.5,1599.5 4393.76,1809
  rectangle net NetC8_2: 381.3,421.3 427.24,510
  rectangle net NetC1_2: 2590,1310 2670,1430
  rectangle net NetC29_2: 1288.19,1520 1430,1561.81
  pour cut-out: 4374.06,1512.52 4374.06,1260.41 4457.5,1260.41 4457.5,1512.52
  pour cut-out: 4847,1125 4935,1125 4935,782.5 4847,782.5
  pour cut-out: 3980.94,1263 3980.94,1098 4400,1098 4400,1263
  pour cut-out: 5252,1158.5 5252,775.5 5331,775.5 5331,1158.5
  pour cut-out: 4840.5,1986.5 4929,1986.5 4929,1653 4840.5,1653
  pour cut-out: 1920,1204.68 1920,1300 1930.43,1300 1930.43,1201.59
  pour cut-out: 1983.68,1507.5 1970,1521.18 1970,1846.5 2093.5,1970 2995,1970 3110,1855 3110,1322.5 3014,1226.5 2440,1226.5 2440,1507.5 2125,1507.5 2125,1620.15 2503,1621.83 2503,1840.62 2196.26,1838.26 2125,1767 2125,1507.5
  pour cut-out: 1690,1110 1690,1300 1820.67,1300 1920,1300 1920,1200 1900,1200 1900,1253.78 1890,1263.78 1890,1270 1829.76,1270 1830.02,1110
  pour cut-out: 504.58,1338.7 504.58,1344.58 510,1350 580,1350 590,1340 590,1210 580,1200 502.35,1200
  pour cut-out: 4901,276.54 4901,782.04 5247.76,782.04 5247.76,276.54
  pour cut-out: 2284,516.91 2772.19,516.91 2772.19,1001 2768.09,1005.09 2284,1005.09
  pour cut-out: 4910.5,1651.5 5252.01,1651.5 5252.01,1130 4910.5,1130
  pour cut-out: 0,1120 870,1120 870,1112.76 870,830 0,830
  pour cut-out: 123.26,189.8 124.04,190.58 723.9,190.58 741.5,208.18 741.5,391.16 722.85,409.8 777.78,409.8 792,395.58 792,363.97 794.03,363.97 810,348 840,348 840,349.8 860.2,370 860.2,576.2 880,596 883.21,592.79 897.21,592.79 897.21,657.21 886.42,668 930.87,668 930.87,561.5 922,561.5 922,358.5 942.37,358.5 991.06,309.8 1070,310 1070,79.5 220.5,79.5 119.43,180.57
  text ".Layer_Name" at 577,-858.49 h60
Bottom Layer:
  pour cut-out: 5394,1251 5753.5,1251 5753.5,748.5 5394,748.5
  pour cut-out: 1919.4,1220 1915.24,1220 1824.76,1220 1824.76,1270 1834.76,1270 1919.4,1270
  pour cut-out: 0,830 0,1120 870,1120 870,830
  pour cut-out: 80,830 1070,830 1070,90 200,90 80,210
  text ".Layer_Name" at 577,-858.49 h60

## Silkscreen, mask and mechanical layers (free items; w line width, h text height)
Top Overlay:
  lines w5: 873.49,1500 916.93,1500 940,1523.07
  text "3.3V" at 980,2000 h30 r90
  text "TX" at 1280,2000 h30 r90
  text "RX" at 1390,2000 h30 r90
  text "GND" at 1180,1990 h30 r90
  text "COMP1" at 880,1960 h30 r90
  text "GPIO12" at 1080,1960 h30 r90
  text "GND" at 5451.5,1889 h30
  text "GND" at 1320,1720 h30
  text "3.3V" at 460,1470 h30 r90
  text "Out+" at 5540,1271 h30
  text "Out-" at 5541,704.5 h30
  text "GND" at 30,690 h30
  text "VBAT" at 30,330 h30
  text "12V" at 3490,280 h30
  text "GND" at 4610,170 h30
  text "Vcc" at 1220,130 h30
  text ".Layer_Name" at 577,-858.49 h30
Bottom Overlay:
  text ".Layer_Name" at 577,-858.49 h60
Top Paste:
  text ".Layer_Name" at 577,-858.49 h60
Bottom Paste:
  text ".Layer_Name" at 577,-858.49 h60
Top Solder:
  text ".Layer_Name" at 577,-858.49 h60
  text ".Layer_Name" at 577,-858.49 h60
Bottom Solder:
  text ".Layer_Name" at 577,-858.49 h60
Drill Guide:
  text ".Layer_Name" at 577,-858.49 h60
M1 Board Outline:
  lines w10: 0,0 5900,0 5900,2100 5900,2310 0,2310 0,0
  text ".Layer_Name" at 577,-858.49 h60
M2 Board Dimensions:
  rectangle: 0,-275 125,-150
  rectangle: 125,-400 500,-275
  lines w7: 0,-275 1000,-275 ; 125,-400 125,-150 ; 250,-400 250,-150 ; 500,-400 500,-150 ; 750,-400 750,-150 ; 0,-400 1000,-400 1000,-150 0,-150 0,-400
  text ".Layer_Name" at 577,-858.49 h60
M3 3D STEP Top:
  text ".Layer_Name" at 577,-858.49 h60
M4 3D STEP Bottom:
  text ".Layer_Name" at 577,-858.49 h60
M5 Assembly Top:
  lines w10: -292,-930.17 6308,-930.17 ; -292,-726.83 6310,-726.83 ; -292,-523.5 -292,-1133.5 3713,-1133.5 6310,-1133.5 6310,-523.5 -291.5,-523.5 -291.5,-1133.5 1284,-1133.5 ; 2173,-1133.5 2173,-523.5 ; 3440,-726.83 3440,-523.5 ; 4280,-726.83 4280,-523.5 ; 4902,-1140 4902,-937.17
  text "COMPONENTS MARKED 'DNP' SHOULD NOT BE POPULATED." at 1153.5,-318.5 h60
  text "ASSEMBLY VARIANT:" at 1153,-434 h60
  text ".VariantName" at 2189,-434 h60
  text "PCB VIEWED FROM TOP SIDE" at -228.5,-655.67 h60
  text "BOARD #:" at 2248,-655.67 h60
  text ".PRJ_Number" at 2793.5,-655.67 h60
  text "REV:" at 3638,-655.67 h60
  text ".PCB_Rev" at 3929.5,-655.67 h60
  text "SVN REV:" at 4476,-655.67 h60
  text ".VersionControl_RevNumber" at 4982,-655.67 h60
  text "TID #:" at 2248,-859 h60
  text ".TID" at 2793.5,-859 h60
  text "PLOT NAME =" at -228.5,-1064.34 h60
  text ".plot_File_Name" at 577,-1064.34 h60
  text "GENERATED    :" at 2250,-1064.34 h60
  text ".Print_Date" at 3119.5,-1064.34 h60
  text ".Print_Time" at 3848.5,-1064.34 h60
  text "TEXAS INSTRUMENTS" at 5113,-1064.34 h60
M6 Assembly Bottom:
  lines w10: -292.5,-727.33 6309.5,-727.33 ; -290.5,-930.67 6309.5,-930.67 ; 1115.5,-1140.5 1115.5,-937.67 ; 1737.5,-727.33 1737.5,-524 ; 2577.5,-727.33 2577.5,-524 ; 3844.5,-1134 3844.5,-524 ; 4733.5,-1134 6309,-1134 6309,-524 -292.5,-524 -292.5,-1134 2304.5,-1134 6309.5,-1134 6309.5,-524
  text "COMPONENTS MARKED 'DNP' SHOULD NOT BE POPULATED." at 6102,-318 h60
  text ".VariantName" at 5058,-434 h60
  text "ASSEMBLY VARIANT:" at 6097,-434 h60
  text ".VersionControl_RevNumber" at 1035.5,-656.17 h60
  text "SVN REV:" at 1541.5,-656.17 h60
  text ".PCB_Rev" at 2088,-656.17 h60
  text "REV:" at 2379.5,-656.17 h60
  text ".PRJ_Number" at 3224,-656.17 h60
  text "BOARD #:" at 3769.5,-656.17 h60
  text "PCB VIEWED FROM BOTTOM SIDE" at 6246,-656.17 h60
  text ".TID" at 3224,-859.5 h60
  text "TID #:" at 3769.5,-859.5 h60
  text "TEXAS INSTRUMENTS" at 904.5,-1064.84 h60
  text ".Print_Time" at 2169,-1064.84 h60
  text ".Print_Date" at 2898,-1064.84 h60
  text "GENERATED    :" at 3767.5,-1064.84 h60
  text ".plot_File_Name" at 5440.5,-1064.84 h60
  text "PLOT NAME =" at 6246,-1064.84 h60
M9 Title Sheet:
  drawing of 57 lines, arcs and shapes, not listed
  text "1" at 739.84,8036.5 h70
  text "2" at 3235.5,8036.5 h70
  text "3" at 5724.84,8036.5 h70
  text "4" at 8231.51,8036.5 h70
  text "5" at 10730.5,8036.5 h70
  text "6" at 13235.5,8036.5 h70
  text "A" at -416.5,6893.5 h70
  text "A" at 14383.5,6893.5 h70
  text "B" at -416.5,4513.5 h70
  text "B" at 14383.5,4513.5 h70
  text "C" at -416.5,2138.5 h70
  text "C" at 14383.5,2138.5 h70
  text "PROJECT TITLE:" at 11343.5,277.5 h45
  text ".PRJ_Title" at 11393.5,144.17 h70
  text "DESIGNED FOR:" at 11343.5,-23.5 h45
  text ".PRJ_Customer" at 11393.5,-163.5 h70
  text "D" at -416.5,-231.5 h70
  text "D" at 14383.5,-231.5 h70
  text "FILE NAME:" at 11343.5,-323.5 h45
  text ".PCB_File_Name_No_Path" at 11393.5,-443.5 h70
  text "Texas Instruments (TI) and/or its licensors do not warrant the accuracy or completeness of this specification" at 6374,-605.34 h45
  text "ENGINEER:" at 11343.5,-613.5 h45
  text "LAYOUT BY:" at 12848.5,-613.5 h45
  text "or any information contained therein. TI and/or its licensors do not warrant that this design will meet" at 6329.01,-718 h45
  text ".PRJ_Engineer" at 11393.5,-768.49 h70
  text ".PCB_Layout" at 12899,-768.49 h70
  text "the specifications, will be suitable for your application or fit for any particular purpose, or will operate in" at 6329.01,-830.67 h45
  text ".Layer_Name" at 577,-858.49 h60
  text "ALTIUM DESIGNER VERSION:" at 12848.5,-923.5 h45
  text "an implementation. TI and/or its licensors do not warrant that the design is production worthy. You should" at 6329.01,-943.33 h45
  text "completely validate and test your design implementation to confirm the system functionality for your application." at 6374,-1056 h45
  text ".print_Scale" at 11393.5,-1056.83 h70
  text ".Application_BuildNumber" at 12899,-1056.83 h70
  text "1" at 739.84,-1263.5 h70
  text "2" at 3235.5,-1263.5 h70
  text "3" at 5724.84,-1263.5 h70
  text "4" at 8231.51,-1263.5 h70
  text "5" at 10730.5,-1263.5 h70
  text "6" at 13235.5,-1263.5 h70
M10 Fab Notes:
  drawing of 189 lines, arcs and shapes, not listed
  text "DESIGN INFORMATION" at 12382.02,6356.17 h60
  text "MIN. TRACK WIDTH:" at 11737.46,6224.05 h60
  text "8" at 12833.7,6224.05 h60
  text "MIL" at 12988.46,6224.05 h60
  text "MIN. CLEARANCE:" at 11737.46,6099.92 h60
  text "0.2" at 12773.7,6099.93 h60
  text "mm" at 12988.46,6099.92 h60
  text "MIN. VIA PAD SIZE:" at 11737.46,5975.8 h60
  text "24" at 12803.71,5975.8 h60
  text "MIL" at 12988.46,5975.8 h60
  text "0.05mm (2MIL)" at 12432.46,5845.9 h60
  text "MINIMUM ANNULAR RING" at 11408.23,5837.67 h60
  text "EXTERNAL" at 13140.46,5837.67 h60
  text "PER" at 11608.23,5727.55 h60
  text "IPC-D-275 CLASS 2 LEVEL C" at 11828.23,5727.54 h60
  text "MIL, HOLES" at 13316.46,5627.07 h60
  text "+/-" at 12924,5618.48 h60
  text "+/-" at 13778,5618.48 h60
  text "REGISTRATION TOLERANCES:" at 11408.23,5617.42 h60
  text "METAL" at 12608,5617.42 h60
  text "5" at 13184.2,5617.42 h60
  text "3" at 14017.2,5617.42 h60
  text "MIL" at 14133.46,5617.42 h60
  text "HOLE SIZE TOLERANCE (UNLESS OTHERWISE SPECIFIED):" at 11408.23,5519.1 h60
  text "+/-" at 13778,5516.23 h60
  text "3" at 14017.2,5515.17 h60
  text "MIL" at 14133.46,5515.17 h60
  text "MATERIAL:" at 11333.46,5377.52 h60
  text "FR-4 High Tg" at 12319.9,5249 h60
  text "X" at 12175.46,5241.01 h60
  text "FR-408" at 11754.46,5236.49 h60
  text "OTHER" at 13242.46,5236.49 h60
  text "62 MIL (1.6mm) +/-10%" at 12074.56,5093.46 h60
  text "X" at 11954.46,5091.01 h60
  text "THICKNESS:" at 11408.23,5085.24 h60
  text "OTHER" at 13359.46,5085.24 h60
  text "TOLERANCE:" at 11408.23,4946.92 h60
  text "X" at 12256.46,4946.92 h60
  text "ANSI IPC-6012 TYPE 3 CLASS 2" at 12434.48,4946.92 h60
  text "OTHER +/-" at 12434.46,4802.73 h60
  text "BOW & TWIST:" at 11408.23,4657.54 h60
  text "X" at 12256.46,4657.54 h60
  text "ANSI IPC-6012 TYPE 3 CLASS 2" at 12434.48,4657.54 h60
  text "OTHER +/-" at 12434.46,4510.85 h60
  text "DRILLING:" at 11333.46,4380.23 h60
  text "NC_DRILL FILES" at 13094.46,4275.04 h60
  text "REFERENCE:" at 11408.23,4271.1 h60
  text "X" at 12065.46,4271.01 h60
  text "AS SHOWN" at 12243.46,4271.1 h60
  text "X" at 12966.46,4271.1 h60
  text "OTHER" at 13392.46,4128.85 h60
  text "PTH COPPER THICKNESS:" at 11407.91,4125.32 h60
  text "X" at 12547.14,4125.32 h60
  text "20-30 um" at 12675.14,4125.32 h60
  text "BOARD FINISH:" at 11333.46,3977.73 h60
  text "SILKSCREEN:" at 11488.68,3867.6 h60
  text "X" at 12446.46,3867.6 h60
  text "TOP" at 12563.46,3867.6 h60
  text "X" at 12956.46,3867.6 h60
  text "BOTTOM" at 13074.46,3867.6 h60
  text "SILKSCREEN COLOR:" at 11488.68,3712.41 h60
  text "X" at 12445.46,3712.41 h60
  text "WHITE" at 12563.46,3712.41 h60
  text "OTHER" at 13074.46,3712.41 h60
  text "X" at 12576.46,3568.96 h60
  text "GREEN" at 12694.46,3568.96 h60
  text "OTHER" at 13312.46,3568.96 h60
  text "SOLDER RESIST COLOR:" at 11488.68,3562.1 h60
  text "X" at 12576.46,3414.71 h60
  text "MATTE" at 12694.46,3414.71 h60
  text "SEMI-GLOSS" at 13312,3414.07 h60
  text "IMMERSION GOLD (ENIG)" at 12394.46,3241.94 h60
  text "ENEPIG" at 13732,3234.72 h60
  text "SURFACE FINISH:" at 11333.46,3233.72 h60
  text "X" at 12216.46,3233.72 h60
  text "IMM. TIN/SILVER OR EQUIV" at 11663,3096.4 h60
  text "OTHER" at 13094.46,3092.47 h60
  text "ARRAY/PANEL:" at 11333.46,2937.09 h60
  text "CUT AND TRIM PER M1 BOARD OUTLINE" at 12394.46,2928.87 h60
  text "N.C. ROUTE" at 12394.46,2792.9 h60
  text "X" at 13082.46,2792.9 h60
  text "V. SCORE" at 13260.46,2792.9 h60
  text "CERTIFICATION:" at 11333.46,2663.77 h60
  text "MATERIALS AND WORKMANSHIP FOR ALL PCBS" at 12058.46,2663.77 h60
  text "TO MEET OR EXCEED THE REQUIREMENTS OF:" at 12058.46,2569.71 h60
  text "X" at 11695.97,2441.08 h60
  text "ANSI IPC-A-600F CLASS ->" at 11823.96,2441.08 h60
  text "X" at 13471.97,2441.08 h60
  text "2" at 13581.96,2441.08 h60
  text "1" at 13266.96,2439.58 h60
  text "3" at 13935.96,2439.58 h60
  text "X" at 12507.97,2293.39 h60
  text "RoHS" at 12635.96,2293.39 h60
  text "OTHER" at 13280.36,2293.39 h60
  text "PER ORDER" at 13677.42,2293.39 h60
  text "ALL BOARDS MUST MEET OR EXCEED UL94-V0 REQUIREMENTS." at 11361,2139.57 h60
  text "PCB MUST BEAR THE UL94V-0 UL REGISTERED MATERIAL ID NUMBER" at 11361,2023.5 h60
  text "ADDITIONAL REQUIREMENTS:" at 11333.46,1854.08 h60
  text "MICROSECTION:" at 11408.23,1746.95 h60
  text "YES" at 12313.96,1746.95 h60
  text "REQUIRED" at 13175.46,1602.62 h60
  text "BARE BOARD ELEC. TEST:" at 11408.23,1599.76 h60
  text "NONE" at 12713.96,1599.76 h60
  text "X" at 13057.46,1599.76 h60
  text "PER ORDER" at 13767.46,1599.76 h60
  text "XX MIL VIAS REQUIRE NON-CONDUCTIVE FILL AND PLANARIZE" at 11576.38,1394.82 h59
  text "XX MIL VIAS REQUIRE CONDUCTIVE FILL AND PLANARIZE" at 11584.38,1290.84 h60
  text "OUTER XX MIL TRACES REQUIRE 50 OHM SINGLE-ENDED IMPEDANCE" at 11583.39,1127.46 h58
  text "LAYER 2 & 3 (INNER LAYERS) XX MIL WIDE, XX MIL SPACE / TRACES REQUIRE 100 OHM DIFFERENTIAL IMPEDANCE" at 11575.39,891.74 h60
  text ".Layer_Name" at 577,-858.49 h60
M11 Gerber Information:
  lines w10: -292,-930.17 6308,-930.17 ; -292,-726.83 6310,-726.83 ; -292,-523.5 -292,-1133.5 3713,-1133.5 6310,-1133.5 6310,-523.5 -291.5,-523.5 -291.5,-1133.5 1284,-1133.5 ; 2173,-1133.5 2173,-523.5 ; 3440,-726.83 3440,-523.5 ; 4280,-726.83 4280,-523.5 ; 4902,-1140 4902,-937.17
  text "ALL ARTWORK VIEWED FROM TOP SIDE" at -228.5,-655.67 h60
  text "BOARD #:" at 2248,-655.67 h60
  text ".PRJ_Number" at 2793.5,-655.67 h60
  text "REV:" at 3638,-655.67 h60
  text ".PCB_Rev" at 3929.5,-655.67 h60
  text "SVN REV:" at 4476,-655.67 h60
  text ".VersionControl_RevNumber" at 4982,-655.67 h60
  text "LAYER NAME =" at -228.5,-858.49 h60
  text "TID #:" at 2248,-859 h60
  text ".TID" at 2793.5,-859 h60
  text "PLOT NAME =" at -228.5,-1064.34 h60
  text ".plot_File_Name" at 577,-1064.34 h60
  text "GENERATED    :" at 2250,-1064.34 h60
  text ".Print_Date" at 3119.5,-1064.34 h60
  text ".Print_Time" at 3848.5,-1064.34 h60
  text "TEXAS INSTRUMENTS" at 5113,-1064.34 h60
M12 Stackup:
  drawing of 191 lines, arcs and shapes, not listed
  text "Layer" at 9797.84,7740 h60
  text "Name" at 10207.76,7740 h60
  text "Material" at 11137.5,7740 h60
  text "Thickness" at 11997.27,7740 h60
  text "Constant" at 12647.1,7740 h60
  text "Board Layer Stack" at 13216.96,7740 h60
  text "1" at 9797.84,7620 h60
  text "Top Overlay" at 10207.76,7620 h60
  text "2" at 9797.84,7500 h60
  text "Top Solder" at 10207.76,7500 h60
  text "Solder Resist" at 11137.5,7500 h60
  text "0.40mil" at 11997.27,7500 h60
  text "3.5" at 12647.1,7500 h60
  text "3" at 9797.84,7380 h60
  text "Top Layer" at 10207.76,7380 h60
  text "Copper" at 11137.5,7380 h60
  text "1.40mil" at 11997.27,7380 h60
  text "4" at 9797.84,7260 h60
  text "Dielectric1" at 10207.76,7260 h60
  text "FR-4" at 11137.5,7260 h60
  text "59.20mil" at 11997.27,7260 h60
  text "4.8" at 12647.1,7260 h60
  text "5" at 9797.84,7140 h60
  text "Bottom Layer" at 10207.76,7140 h60
  text "Copper" at 11137.5,7140 h60
  text "1.40mil" at 11997.27,7140 h60
  text "6" at 9797.84,7020 h60
  text "Bottom Solder" at 10207.76,7020 h60
  text "Solder Resist" at 11137.5,7020 h60
  text "0.40mil" at 11997.27,7020 h60
  text "3.5" at 12647.1,7020 h60
  text "7" at 9797.84,6900 h60
  text "Bottom Overlay" at 10207.76,6900 h60
  text ".Layer_Name" at 577,-858.49 h60
M13 Component Bodies Top:
  text ".Layer_Name" at 577,-858.49 h60
M14 Component Bodies Bottom:
  text ".Layer_Name" at 577,-858.49 h60
M15 Courtyards Top:
  text ".Layer_Name" at 577,-858.49 h60
M16 Courtyards Bottom:
  text ".Layer_Name" at 577,-858.49 h60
